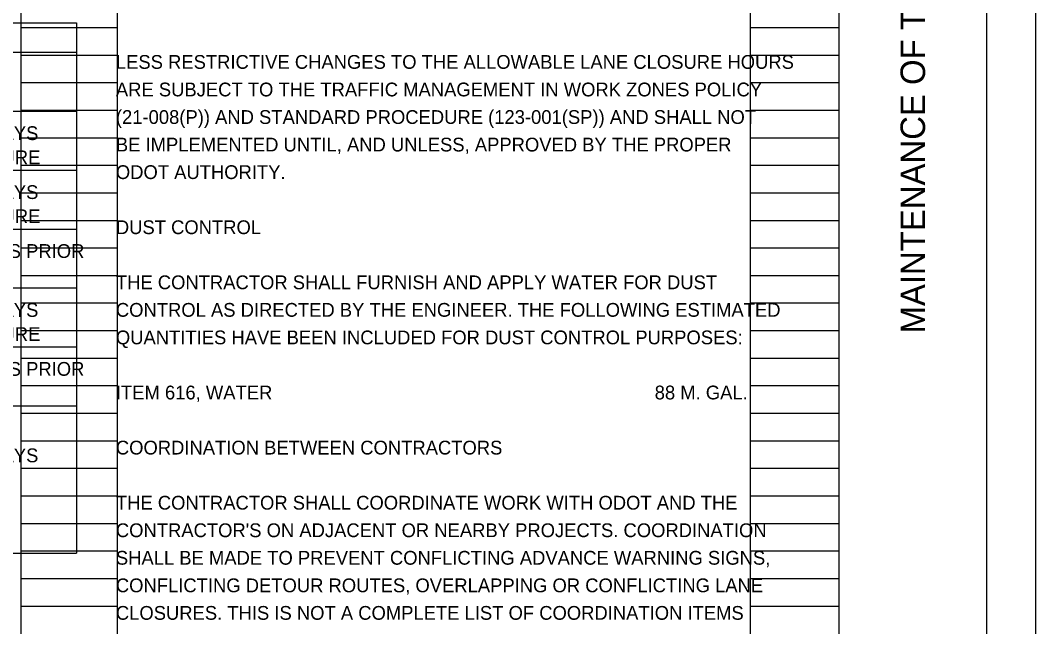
# Model space of a CAD drawing. Extents: x -26.4 to 34, y 0 to 22.
# Drawn here: x 23.67 to 34, y 6.37 to 12.53 of the extents above; entities that cross this region are included whole.
import ezdxf

# ---------------------------------------------------------------- set-up
doc = ezdxf.new("R2010")
doc.units = 0
for name, color, linetype in [('SH_Border', 7, 'Continuous'), ('SH_Cut_Line', 7, 'Continuous'), ('SH_Data', 7, 'Continuous'), ('SH_Text', 7, 'Continuous')]:
    doc.layers.add(name, color=color, linetype=linetype)

msp = doc.modelspace()

# ---------------------------------------------------------------- linework, layer by layer
at = {"layer": 'SH_Border'}
msp.add_line((32, 0.5), (32, 21.5), dxfattribs=at)
msp.add_lwpolyline([(1.5, 21.5), (33.5, 21.5), (33.5, 0.5), (1.5, 0.5)], close=True, dxfattribs=at)
at = {"layer": 'SH_Cut_Line'}
msp.add_lwpolyline([(0, 0), (34, 0), (34, 22), (0, 22)], close=True, dxfattribs=at)
at = {"layer": 'SH_Data'}
for p, q in [((23.68, 0.98), (23.68, 21.14)), ((24.66, 0.98), (24.66, 21.14)), ((31.1, 0.98), (31.1, 21.14)), ((32, 0.98), (32, 21.14)), ((23.68, 12.46), (24.66, 12.46)), ((31.1, 12.46), (32, 12.46)), ((23.68, 12.18), (24.66, 12.18)), ((31.1, 12.18), (32, 12.18)), ((23.68, 11.9), (24.66, 11.9)), ((31.1, 11.9), (32, 11.9)), ((23.68, 11.62), (24.66, 11.62)), ((31.1, 11.62), (32, 11.62)), ((23.68, 11.34), (24.66, 11.34)), ((31.1, 11.34), (32, 11.34)), ((23.68, 11.06), (24.66, 11.06)), ((31.1, 11.06), (32, 11.06)), ((23.68, 10.78), (24.66, 10.78)), ((31.1, 10.78), (32, 10.78)), ((23.68, 10.5), (24.66, 10.5)), ((31.1, 10.5), (32, 10.5)), ((23.68, 10.22), (24.66, 10.22)), ((31.1, 10.22), (32, 10.22)), ((23.68, 9.94), (24.66, 9.94)), ((31.1, 9.94), (32, 9.94)), ((23.68, 9.66), (24.66, 9.66)), ((31.1, 9.66), (32, 9.66)), ((23.68, 9.38), (24.66, 9.38)), ((31.1, 9.38), (32, 9.38)), ((23.68, 9.1), (24.66, 9.1)), ((31.1, 9.1), (32, 9.1)), ((23.68, 8.82), (24.66, 8.82)), ((31.1, 8.82), (32, 8.82)), ((23.68, 8.54), (24.66, 8.54)), ((31.1, 8.54), (32, 8.54)), ((23.68, 8.26), (24.66, 8.26)), ((31.1, 8.26), (32, 8.26)), ((23.68, 7.98), (24.66, 7.98)), ((31.1, 7.98), (32, 7.98)), ((23.68, 7.7), (24.66, 7.7)), ((31.1, 7.7), (32, 7.7)), ((23.68, 7.42), (24.66, 7.42)), ((31.1, 7.42), (32, 7.42)), ((23.68, 7.14), (24.66, 7.14)), ((31.1, 7.14), (32, 7.14)), ((23.68, 6.86), (24.66, 6.86)), ((31.1, 6.86), (32, 6.86)), ((23.68, 6.58), (24.66, 6.58)), ((31.1, 6.58), (32, 6.58))]:
    msp.add_line(p, q, dxfattribs=at)
at = {"layer": 'SH_Text'}
for p, q in [((17.266, 12.508), (24.244, 12.508)), ((24.244, 12.508), (24.244, 7.118)), ((17.266, 12.209), (24.244, 12.209)), ((17.266, 11.61), (24.244, 11.61)), ((19.332, 11.011), (24.244, 11.011)), ((19.332, 10.412), (24.244, 10.412)), ((17.266, 9.813), (24.244, 9.813)), ((19.332, 9.214), (24.244, 9.214)), ((17.266, 8.615), (24.244, 8.615)), ((17.266, 7.118), (24.244, 7.118))]:
    msp.add_line(p, q, dxfattribs=at)

# ---------------------------------------------------------------- texts
at = {"layer": 'SH_Data'}
msp.add_text('MAINTENANCE OF TRAFFIC - GENERAL NOTES', height=0.25, rotation=90, dxfattribs=at).set_placement((32.875, 9.35))
at = {"layer": 'SH_Text'}
for s, p in [('LESS RESTRICTIVE CHANGES TO THE ALLOWABLE LANE CLOSURE HOURS ', (24.643, 12.04)), ('ARE SUBJECT TO THE TRAFFIC MANAGEMENT IN WORK ZONES POLICY ', (24.643, 11.76)), ('(21-008(P)) AND STANDARD PROCEDURE (123-001(SP)) AND SHALL NOT ', (24.643, 11.48)), ('21 CALENDAR DAYS ', (22.013, 11.316)), ('BE IMPLEMENTED UNTIL, AND UNLESS, APPROVED BY THE PROPER ', (24.643, 11.2)), ('PRIOR TO CLOSURE', (22.013, 11.071)), ('ODOT AUTHORITY.', (24.643, 10.92)), ('14 CALENDAR DAYS ', (22.013, 10.717)), ('PRIOR TO CLOSURE', (22.013, 10.472)), ('DUST CONTROL', (24.643, 10.36)), ('4 BUSINESS DAYS PRIOR ', (22.013, 10.118)), ('THE CONTRACTOR SHALL FURNISH AND APPLY WATER FOR DUST ', (24.643, 9.8)), ('14 CALENDAR DAYS ', (22.013, 9.519)), ('CONTROL AS DIRECTED BY THE ENGINEER. THE FOLLOWING ESTIMATED ', (24.643, 9.52)), ('PRIOR TO CLOSURE', (22.013, 9.274)), ('QUANTITIES HAVE BEEN INCLUDED FOR DUST CONTROL PURPOSES:', (24.643, 9.24)), ('5 BUSINESS DAYS PRIOR ', (22.013, 8.92)), ('ITEM 616, WATER', (24.643, 8.68)), ('88 M. GAL.', (30.124, 8.68)), ('14 CALENDAR DAYS ', (22.013, 8.041)), ('COORDINATION BETWEEN CONTRACTORS', (24.643, 8.12)), ('THE CONTRACTOR SHALL COORDINATE WORK WITH ODOT AND THE ', (24.643, 7.56)), ("CONTRACTOR'S ON ADJACENT OR NEARBY PROJECTS. COORDINATION ", (24.643, 7.28)), ('SHALL BE MADE TO PREVENT CONFLICTING ADVANCE WARNING SIGNS, ', (24.643, 7)), ('CONFLICTING DETOUR ROUTES, OVERLAPPING OR CONFLICTING LANE ', (24.643, 6.72)), ('CLOSURES. THIS IS NOT A COMPLETE LIST OF COORDINATION ITEMS ', (24.643, 6.44))]:
    msp.add_text(s, height=0.14, dxfattribs=at).set_placement(p)

doc.saveas('drawing.dxf')
